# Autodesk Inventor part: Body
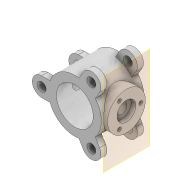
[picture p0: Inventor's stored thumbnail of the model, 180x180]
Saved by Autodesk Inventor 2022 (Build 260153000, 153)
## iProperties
Created: 2019-03
Part Number: Body
Material: Generic
Document SubType Name: Modeling
Designer: LENOVO-CADCIM
Density: 1 g/cm^3
Appearance: Default
Author: LENOVO-CADCIM
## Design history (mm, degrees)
sketch "Sketch1"
  geometry: C1 r 140 at (0, 0); C2 r 97 at (0, 0); 1 further point
  constraints: 2 centre point, 2 coincident
  dimensions: "d0" = 194 diameter of C2; "d1" = 280 diameter of C1
extrude "Extrusion1" new body sketch "Sketch1" stored distance "d2" = 225; taper "d3" = 0 deg
sketch "Sketch2"
  geometry: L1 (0, 0)-(-428, 0); L2 (-130.767, 50)-(-175, 50); L3 (-130.767, -50)-(-175, -50); C1 r 23.5 at (-175, 0); A1 r 175 centre (0, 0) between (-175, 0) and (-175, 0); A2 r 140 centre (0, 0) between (-130.767, 50) and (-130.767, -50) reference; A3 r 50 centre (-175, 0) between (-175, 50) and (-175, -50); 1 further point
  constraints: 6 end point, 6 point on circle, 3 centre point, 3 horizontal, 2 tangent, 1 coincident, 1 point on line, 1 other
  dimensions: "d4" = 350 diameter of A1; "d5" = 50 radius of A3; "d6" = 47 diameter of C1
extrude "Extrusion2" join sketch "Sketch2" distance "d7" = 32; taper "d8" = 0 deg
pattern_circular "Circular Pattern1" dims angle "d10" = 360 deg
mirror "Mirror1"
workplane "Work Plane1"
sketch "Sketch3"
  geometry: C1 r 100 at (0, 0); 1 further point
  constraints: 1 centre point, 1 coincident
  dimensions: "d13" = 200 diameter of C1
extrude "Extrusion3" join sketch "Sketch3" stored distance "d14" = 32; taper "d15" = 0 deg
sketch "Sketch4" dims "d16" = 150
  geometry: L1 (0, 0)-(102, 0); C1 r 10 at (75, 0); 2 further points
  constraints: 2 coincident, 2 end point, 1 centre point, 1 horizontal, 1 horizontal alignment, 1 point on line, 2 other
  dimensions: "d34" = 20 diameter of C1
sketch "Sketch5"
  geometry: C1 r 100 at (0, 0) reference; 2 further points
  constraints: 1 coincident
hole "Hole2" sketch "Sketch5" at (0, 0) diameter "d27" = 56; stored, may be unused: countersink angle "d31" = 90 deg, drill point angle "d33" = 118 deg; dims "d28" = 6, "d29" = 100, "d30" = 25, "d32" = 310
extrude "Extrusion4" cut sketch "Sketch4" distance "d35" = 40; taper "d36" = 0 deg
pattern_circular "Circular Pattern3" dims angle "d38" = 360 deg
body "Solid1"
